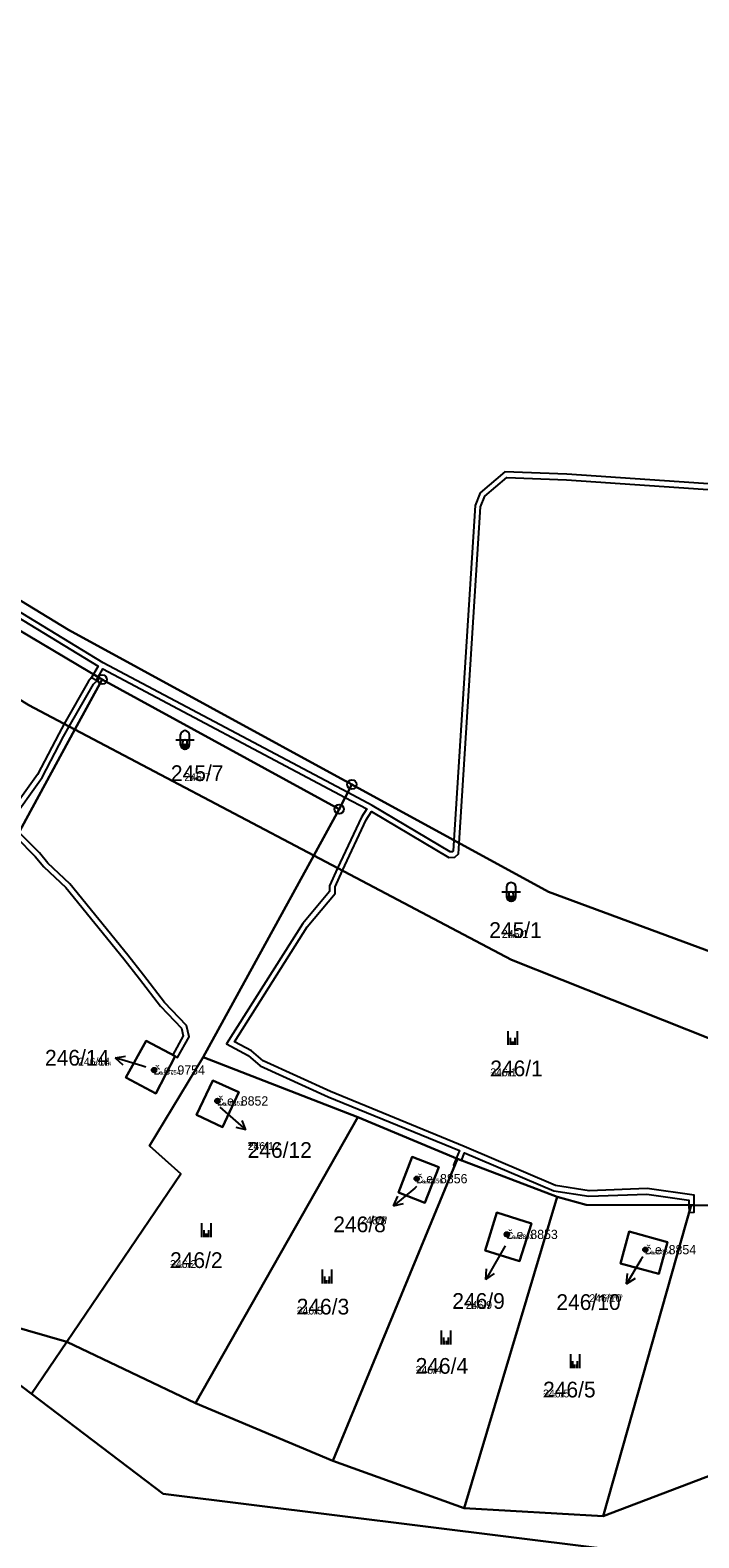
# Model space of a CAD drawing. Extents: x -759873 to -758487, y -975024 to -973516.
# Drawn here: x -759072.7 to -759000.3, y -974638.1 to -974475 of the extents above; entities that cross this region are included whole.
import ezdxf

# ---------------------------------------------------------------- set-up
doc = ezdxf.new("R2010")
doc.units = 0
for name, color, linetype in [('KAT_02_hranice parcel', 7, 'Continuous'), ('KAT_03_1000_st čísla parcelní', 7, 'Continuous'), ('KAT_03_1000_čísla parcelní', 7, 'Continuous'), ('KAT_03_1000_čísla popisná', 7, 'Continuous'), ('KAT_03_250_st čísla parcelní', 7, 'Continuous'), ('KAT_03_250_čísla parcelní', 7, 'Continuous'), ('KAT_03_250_čísla popisná', 7, 'Continuous'), ('KAT_03_500_st čísla parcelní', 7, 'Continuous'), ('KAT_03_500_čísla parcelní', 7, 'Continuous'), ('KAT_03_500_čísla popisná', 7, 'Continuous'), ('KAT_05_1000_značky kultur', 7, 'Continuous'), ('KAT_05_250_značky kultur', 7, 'Continuous'), ('KAT_05_500_značky kultur', 7, 'Continuous'), ('KAT_07_1000_značky budov', 7, 'Continuous'), ('KAT_07_250_značky budov', 7, 'Continuous'), ('KAT_07_500_značky budov', 7, 'Continuous'), ('KAT_10_věcná břemena', 7, 'Continuous'), ('KAT_11_značky bodu BP', 7, 'Continuous'), ('KAT_12_pomocná šipka', 7, 'Continuous'), ('KAT_14_plocha_budovy', 7, 'Continuous'), ('KAT_14_plocha_pozemek', 7, 'Continuous')]:
    doc.layers.add(name, color=color, linetype=linetype)

msp = doc.modelspace()

# ---------------------------------------------------------------- linework, layer by layer
at = {"layer": 'KAT_02_hranice parcel'}
for p, q in [((-759083.78, -974533.99), (-759064.86, -974545.21)), ((-759067.83, -974550.62), (-759064.86, -974545.21)), ((-759064.86, -974545.21), (-759039.21, -974559.23)), ((-759067.83, -974550.62), (-759041.97, -974564.24)), ((-759037.83, -974556.56), (-759039.21, -974559.23)), ((-759039.21, -974559.23), (-759041.97, -974564.24)), ((-759041.97, -974564.24), (-759053.94, -974586.07)), ((-759053.94, -974586.07), (-759037.2, -974592.53)), ((-759054.75, -974623.47), (-759037.2, -974592.53)), ((-759037.2, -974592.53), (-759026.41, -974597.05)), ((-759039.89, -974629.72), (-759026.41, -974597.05)), ((-759026.41, -974597.05), (-759015.6, -974601.17)), ((-759025.68, -974634.84), (-759015.6, -974601.17)), ((-759010.62, -974635.71), (-759001.08, -974602.07)), ((-759001.08, -974602.07), (-758984.89, -974602.12)), ((-759068.68, -974616.85), (-759072.53, -974622.47)), ((-759068.68, -974616.85), (-759054.75, -974623.47)), ((-759054.75, -974623.47), (-759039.89, -974629.72)), ((-759039.89, -974629.72), (-759025.68, -974634.84)), ((-759025.68, -974634.84), (-759010.62, -974635.71))]:
    msp.add_line(p, q, dxfattribs=at)
for points in [[(-759159.14, -974477.67), (-759138.76, -974497.06), (-759068.5, -974539.82), (-759037.83, -974556.56)], [(-759087, -974539.27), (-759072.82, -974547.99), (-759067.83, -974550.62)], [(-759100.16, -974608.12), (-759088.78, -974587.22), (-759079.24, -974570.06), (-759074.96, -974563.7), (-759067.83, -974550.62)], [(-759037.83, -974556.56), (-759016.55, -974568.17), (-758996.05, -974575.76)], [(-758998.76, -974584.19), (-759020.55, -974575.52), (-759041.97, -974564.24)], [(-759060.11, -974584.3), (-759062.32, -974588.27), (-759059.06, -974589.97), (-759056.96, -974585.95), (-759060.11, -974584.3)], [(-759072.53, -974622.47), (-759085.12, -974612.91), (-759119.49, -974608.48), (-759126.45, -974601.07), (-759123.88, -974586.97)], [(-759053.94, -974586.07), (-759059.73, -974595.66), (-759056.36, -974598.66), (-759068.68, -974616.85)], [(-759050.06, -974589.86), (-759051.86, -974593.64), (-759054.65, -974592.31), (-759052.9, -974588.58), (-759050.06, -974589.86)], [(-759028.4, -974597.95), (-759029.93, -974601.83), (-759032.79, -974600.7), (-759031.32, -974596.83), (-759028.4, -974597.95)], [(-759015.6, -974601.17), (-759012.48, -974602.03), (-759001.08, -974602.07)], [(-759019.7, -974608.14), (-759023.41, -974606.96), (-759022.14, -974602.86), (-759018.4, -974604.06), (-759019.7, -974608.14)], [(-759010.62, -974635.71), (-758989.44, -974627.68), (-758984.89, -974602.12)], [(-759003.65, -974606.07), (-759004.59, -974609.51), (-759008.75, -974608.38), (-759007.8, -974604.9), (-759003.65, -974606.07)], [(-759068.68, -974616.85), (-759079.63, -974613.7), (-759088.47, -974610.92), (-759100.16, -974608.12)], [(-759072.53, -974622.47), (-759058.27, -974633.29), (-759011.32, -974639.13), (-758985.91, -974649.95)]]:
    msp.add_lwpolyline(points, dxfattribs=at)
at = {"layer": 'KAT_03_1000_čísla popisná'}
for centre in [(-759059.25, -974587.45), (-759052.39, -974590.79), (-759030.82, -974599.2), (-759021.04, -974605.23), (-759006.06, -974606.88)]:
    msp.add_circle(centre, 0.25, dxfattribs=at)
at = {"layer": 'KAT_03_250_čísla popisná'}
for centre in [(-759059.25, -974587.45), (-759052.39, -974590.79), (-759030.82, -974599.2), (-759021.04, -974605.23), (-759006.06, -974606.88)]:
    msp.add_circle(centre, 0.0625, dxfattribs=at)
at = {"layer": 'KAT_03_500_čísla popisná'}
for centre in [(-759059.25, -974587.45), (-759052.39, -974590.79), (-759030.82, -974599.2), (-759021.04, -974605.23), (-759006.06, -974606.88)]:
    msp.add_circle(centre, 0.125, dxfattribs=at)
at = {"layer": 'KAT_05_1000_značky kultur'}
for p, q in [((-759056.41, -974551.24), (-759056.41, -974552.24)), ((-759055.41, -974552.24), (-759055.41, -974551.24)), ((-759056.91, -974551.74), (-759054.91, -974551.74)), ((-759021.09, -974567.68), (-759021.09, -974568.68)), ((-759020.09, -974568.68), (-759020.09, -974567.68)), ((-759021.59, -974568.18), (-759019.59, -974568.18)), ((-759020.91, -974584.73), (-759020.91, -974583.23)), ((-759019.91, -974584.73), (-759019.91, -974583.23)), ((-759054.08, -974605.51), (-759054.08, -974604.01)), ((-759053.08, -974605.51), (-759053.08, -974604.01)), ((-759041.01, -974610.54), (-759041.01, -974609.04)), ((-759040.01, -974610.54), (-759040.01, -974609.04)), ((-759028.13, -974617.12), (-759028.13, -974615.62)), ((-759027.13, -974617.12), (-759027.13, -974615.62)), ((-759014.14, -974619.68), (-759014.14, -974618.18)), ((-759013.14, -974619.68), (-759013.14, -974618.18))]:
    msp.add_line(p, q, dxfattribs=at)
for centre, start, end in [((-759055.91, -974551.24), 0, 180), ((-759055.91, -974552.24), 180, 359.9879), ((-759020.59, -974567.68), 0, 180), ((-759020.59, -974568.68), 180, 359.9879)]:
    msp.add_arc(centre, 0.5, start, end, dxfattribs=at)
at = {"layer": 'KAT_05_250_značky kultur'}
for p, q in [((-759056.16, -974552.49), (-759055.66, -974552.49)), ((-759056.04, -974552.37), (-759056.04, -974552.62)), ((-759055.78, -974552.62), (-759055.78, -974552.37)), ((-759020.84, -974568.93), (-759020.34, -974568.93)), ((-759020.72, -974568.81), (-759020.72, -974569.06)), ((-759020.46, -974569.06), (-759020.46, -974568.81)), ((-759020.53, -974584.73), (-759020.53, -974584.35)), ((-759020.28, -974584.73), (-759020.28, -974584.35)), ((-759053.7, -974605.51), (-759053.7, -974605.14)), ((-759053.45, -974605.51), (-759053.45, -974605.14)), ((-759040.63, -974610.54), (-759040.63, -974610.17)), ((-759040.38, -974610.54), (-759040.38, -974610.17)), ((-759027.75, -974617.12), (-759027.75, -974616.74)), ((-759027.5, -974617.12), (-759027.5, -974616.74)), ((-759013.76, -974619.68), (-759013.76, -974619.31)), ((-759013.51, -974619.68), (-759013.51, -974619.31))]:
    msp.add_line(p, q, dxfattribs=at)
for centre, start, end in [((-759055.91, -974552.37), 0, 180), ((-759055.91, -974552.62), 180, 359.9879), ((-759020.59, -974568.81), 0, 180), ((-759020.59, -974569.06), 180, 359.9879)]:
    msp.add_arc(centre, 0.125, start, end, dxfattribs=at)
at = {"layer": 'KAT_05_500_značky kultur'}
for p, q in [((-759056.41, -974552.24), (-759055.41, -974552.24)), ((-759056.16, -974551.99), (-759056.16, -974552.49)), ((-759055.66, -974552.49), (-759055.66, -974551.99)), ((-759021.09, -974568.68), (-759020.09, -974568.68)), ((-759020.84, -974568.43), (-759020.84, -974568.93)), ((-759020.34, -974568.93), (-759020.34, -974568.43)), ((-759020.66, -974584.73), (-759020.66, -974583.98)), ((-759020.16, -974584.73), (-759020.16, -974583.98)), ((-759053.83, -974605.51), (-759053.83, -974604.76)), ((-759053.33, -974605.51), (-759053.33, -974604.76)), ((-759040.76, -974610.54), (-759040.76, -974609.79)), ((-759040.26, -974610.54), (-759040.26, -974609.79)), ((-759027.88, -974617.12), (-759027.88, -974616.37)), ((-759027.38, -974617.12), (-759027.38, -974616.37)), ((-759013.89, -974619.68), (-759013.89, -974618.93)), ((-759013.39, -974619.68), (-759013.39, -974618.93))]:
    msp.add_line(p, q, dxfattribs=at)
for centre, start, end in [((-759055.91, -974551.99), 0, 180), ((-759055.91, -974552.49), 180, 359.9879), ((-759020.59, -974568.43), 0, 180), ((-759020.59, -974568.93), 180, 359.9879)]:
    msp.add_arc(centre, 0.25, start, end, dxfattribs=at)
at = {"layer": 'KAT_07_1000_značky budov'}
for centre in [(-759059.26, -974587.45), (-759052.4, -974590.79), (-759030.83, -974599.2), (-759021.05, -974605.23), (-759006.07, -974606.88)]:
    msp.add_circle(centre, 0.175, dxfattribs=at)
at = {"layer": 'KAT_07_250_značky budov'}
for centre in [(-759059.25, -974587.45), (-759052.39, -974590.79), (-759030.82, -974599.2), (-759021.04, -974605.23), (-759006.06, -974606.88)]:
    msp.add_circle(centre, 0.0437, dxfattribs=at)
at = {"layer": 'KAT_07_500_značky budov'}
for centre in [(-759059.25, -974587.45), (-759052.39, -974590.79), (-759030.82, -974599.2), (-759021.04, -974605.23), (-759006.06, -974606.88)]:
    msp.add_circle(centre, 0.0875, dxfattribs=at)
at = {"layer": 'KAT_10_věcná břemena'}
for points in [[(-759099.57, -974522.91), (-759065.31, -974543.77), (-759065.82, -974544.64), (-759066.02, -974544.99), (-759065.5, -974545.29), (-759065.3, -974544.95), (-759064.79, -974544.07), (-759038.55, -974557.96), (-759036.23, -974559.19), (-759036.8, -974560.08), (-759039.38, -974565.6), (-759040.26, -974567.51), (-759040.24, -974568.15), (-759043.14, -974571.6), (-759051.41, -974584.63), (-759049.05, -974585.89), (-759047.77, -974586.98), (-759040.4, -974590.34), (-759026.18, -974596.16), (-759026.53, -974597), (-759026.41, -974597.05), (-759025.97, -974597.22), (-759025.63, -974596.4), (-759015.95, -974600.53), (-759012.19, -974601.1), (-759005.89, -974600.86), (-759001.36, -974601.51), (-759001.34, -974602.07), (-759000.76, -974602.07), (-759000.76, -974600.99), (-759005.85, -974600.26), (-759012.15, -974600.5), (-759015.79, -974599.95), (-759025.67, -974595.72), (-759040.16, -974589.78), (-759047.45, -974586.46), (-759048.71, -974585.39), (-759050.55, -974584.41), (-759042.66, -974571.96), (-759039.64, -974568.37), (-759039.66, -974567.63), (-759038.84, -974565.88), (-759036.28, -974560.38), (-759035.7, -974559.49), (-759027.34, -974564.45), (-759026.7, -974564.43), (-759026.27, -974564.06), (-759026.2, -974562.91), (-759026.78, -974562.59), (-759026.85, -974563.76), (-759026.94, -974563.83), (-759027.18, -974563.85), (-759035.65, -974558.82), (-759038.28, -974557.43), (-759064.75, -974543.41), (-759099.77, -974522.09)], [(-758968.02, -974526.18), (-759014.55, -974523.01), (-759021.27, -974522.74), (-759023.95, -974525.01), (-759024.49, -974526.4), (-759026.78, -974562.59), (-759026.2, -974562.91), (-759023.89, -974526.52), (-759023.45, -974525.37), (-759021.07, -974523.34), (-759014.59, -974523.61), (-758968.08, -974526.78)], [(-759074.87, -974560.71), (-759071.36, -974555.82), (-759069.07, -974551.39), (-759068.45, -974550.3), (-759065.82, -974545.7), (-759065.24, -974545.18), (-759065.17, -974545.03), (-759065.82, -974544.64), (-759066.02, -974544.99), (-759066.34, -974545.4), (-759068.97, -974550.02), (-759069.57, -974551.07), (-759071.86, -974555.5), (-759075.29, -974560.28)], [(-759074.18, -974562.27), (-759072.11, -974564.37), (-759071.18, -974565.47), (-759068.82, -974567.72), (-759062.54, -974575.43), (-759060.84, -974577.57), (-759058.57, -974580.55), (-759056.28, -974582.92), (-759056.1, -974583.76), (-759057.22, -974585.81), (-759056.96, -974585.95), (-759056.7, -974586.09), (-759055.46, -974583.84), (-759055.74, -974582.62), (-759058.11, -974580.15), (-759060.38, -974577.19), (-759062.08, -974575.03), (-759068.38, -974567.32), (-759070.74, -974565.07), (-759071.67, -974563.97), (-759073.88, -974561.72)]]:
    msp.add_lwpolyline(points, dxfattribs=at)
for points in [[(-759026.71, -974597.78), (-759026.41, -974597.05), (-759026.53, -974597), (-759026.83, -974597.73)], [(-759001.34, -974602.07), (-759001.3, -974602.86), (-759001.08, -974602.07)], [(-759001.3, -974602.86), (-759000.76, -974602.84), (-759000.76, -974602.07), (-759001.08, -974602.07)]]:
    msp.add_lwpolyline(points, close=True, dxfattribs=at)
at = {"layer": 'KAT_11_značky bodu BP'}
for centre, radius in [((-759064.86, -974545.21), 0.5), ((-759064.86, -974545.21), 0.0303), ((-759037.83, -974556.56), 0.5), ((-759037.83, -974556.56), 0.0303), ((-759039.21, -974559.23), 0.5), ((-759039.21, -974559.23), 0.0303)]:
    msp.add_circle(centre, radius, dxfattribs=at)
at = {"layer": 'KAT_12_pomocná šipka'}
for p, q in [((-759063.45, -974586.12), (-759062.35, -974585.94)), ((-759060.58, -974587), (-759063.45, -974586.12)), ((-759063.45, -974586.12), (-759062.64, -974586.89)), ((-759060.16, -974587.13), (-759060.58, -974587)), ((-759052.13, -974591.46), (-759051.56, -974591.96)), ((-759051.56, -974591.96), (-759049.3, -974593.93)), ((-759049.3, -974593.93), (-759050.38, -974593.65)), ((-759049.3, -974593.93), (-759049.72, -974592.89)), ((-759031.02, -974600.21), (-759033.32, -974602.14)), ((-759030.84, -974600.06), (-759031.02, -974600.21)), ((-759033.32, -974602.14), (-759032.87, -974601.11)), ((-759033.32, -974602.14), (-759032.23, -974601.88)), ((-759021.24, -974606.48), (-759021.82, -974607.49)), ((-759021.82, -974607.49), (-759023.32, -974610.09)), ((-759006.54, -974607.99), (-759008.09, -974610.56)), ((-759006.34, -974607.65), (-759006.54, -974607.99)), ((-759023.32, -974610.09), (-759023.25, -974608.97)), ((-759023.32, -974610.09), (-759022.39, -974609.47)), ((-759008.09, -974610.56), (-759008, -974609.45)), ((-759008.09, -974610.56), (-759007.14, -974609.96))]:
    msp.add_line(p, q, dxfattribs=at)
at = {"layer": 'KAT_14_plocha_budovy'}
for points in [[(-759062.32, -974588.27), (-759059.06, -974589.97), (-759056.96, -974585.95), (-759060.11, -974584.3)], [(-759054.65, -974592.31), (-759051.86, -974593.64), (-759050.06, -974589.86), (-759052.9, -974588.58)], [(-759032.79, -974600.7), (-759029.93, -974601.83), (-759028.4, -974597.95), (-759031.32, -974596.83)], [(-759023.41, -974606.96), (-759019.7, -974608.14), (-759018.4, -974604.06), (-759022.14, -974602.86)], [(-759008.75, -974608.38), (-759004.59, -974609.51), (-759003.65, -974606.07), (-759007.8, -974604.9)]]:
    msp.add_lwpolyline(points, close=True, dxfattribs=at)
at = {"layer": 'KAT_14_plocha_pozemek'}
for points in [[(-759164.42, -974455.5), (-759159.14, -974477.67), (-759138.76, -974497.06), (-759068.5, -974539.82), (-759037.83, -974556.56), (-759016.55, -974568.17), (-758996.05, -974575.76)], [(-758985.91, -974649.95), (-759011.32, -974639.13), (-759058.27, -974633.29), (-759072.53, -974622.47), (-759085.12, -974612.91), (-759119.49, -974608.48), (-759126.45, -974601.07), (-759123.88, -974586.97), (-759138.78, -974574.64), (-759149.95, -974565.4), (-759151.3, -974564.28), (-759155.66, -974538.03), (-759168.27, -974530.82)]]:
    msp.add_lwpolyline(points, dxfattribs=at)
for points in [[(-759100.28, -974524), (-759083.78, -974533.99), (-759064.86, -974545.21), (-759039.21, -974559.23), (-759037.83, -974556.56), (-759068.5, -974539.82), (-759138.76, -974497.06), (-759159.14, -974477.67), (-759150.51, -974493.42), (-759122.84, -974510.23)], [(-759087, -974539.27), (-759072.82, -974547.99), (-759067.83, -974550.62), (-759064.86, -974545.21), (-759083.78, -974533.99)], [(-759067.83, -974550.62), (-759072.82, -974547.99), (-759087, -974539.27), (-759093.17, -974549.44), (-759100.94, -974559.67), (-759106.9, -974566.95), (-759110.32, -974570.69), (-759122.47, -974587.73), (-759119.12, -974590.77), (-759122.45, -974602.82), (-759100.16, -974608.12), (-759088.78, -974587.22), (-759079.24, -974570.06), (-759074.96, -974563.7)], [(-759067.83, -974550.62), (-759041.97, -974564.24), (-759039.21, -974559.23), (-759064.86, -974545.21)], [(-759053.94, -974586.07), (-759041.97, -974564.24), (-759067.83, -974550.62), (-759074.96, -974563.7), (-759079.24, -974570.06), (-759088.78, -974587.22), (-759100.16, -974608.12), (-759088.47, -974610.92), (-759079.63, -974613.7), (-759068.68, -974616.85), (-759056.36, -974598.66), (-759059.73, -974595.66)], [(-759039.21, -974559.23), (-759041.97, -974564.24), (-759020.55, -974575.52), (-758998.76, -974584.19), (-758996.05, -974575.76), (-759016.55, -974568.17), (-759037.83, -974556.56)], [(-758968.42, -974607.24), (-758984.03, -974596.47), (-758998.76, -974584.19), (-759020.55, -974575.52), (-759041.97, -974564.24), (-759053.94, -974586.07), (-759037.2, -974592.53), (-759026.41, -974597.05), (-759015.6, -974601.17), (-759012.48, -974602.03), (-759001.08, -974602.07), (-758984.89, -974602.12)], [(-759060.11, -974584.3), (-759062.32, -974588.27), (-759059.06, -974589.97), (-759056.96, -974585.95)], [(-759060.11, -974584.3), (-759056.96, -974585.95), (-759059.06, -974589.97), (-759062.32, -974588.27)], [(-759088.47, -974610.92), (-759100.16, -974608.12), (-759122.45, -974602.82), (-759119.12, -974590.77), (-759122.47, -974587.73), (-759123.88, -974586.97), (-759126.45, -974601.07), (-759119.49, -974608.48), (-759085.12, -974612.91), (-759072.53, -974622.47), (-759068.68, -974616.85), (-759079.63, -974613.7)], [(-759053.94, -974586.07), (-759059.73, -974595.66), (-759056.36, -974598.66), (-759068.68, -974616.85), (-759054.75, -974623.47), (-759037.2, -974592.53)], [(-759050.06, -974589.86), (-759051.86, -974593.64), (-759054.65, -974592.31), (-759052.9, -974588.58)], [(-759050.06, -974589.86), (-759052.9, -974588.58), (-759054.65, -974592.31), (-759051.86, -974593.64)], [(-759039.89, -974629.72), (-759026.41, -974597.05), (-759037.2, -974592.53), (-759054.75, -974623.47)], [(-759025.68, -974634.84), (-759015.6, -974601.17), (-759026.41, -974597.05), (-759039.89, -974629.72)], [(-759028.4, -974597.95), (-759029.93, -974601.83), (-759032.79, -974600.7), (-759031.32, -974596.83)], [(-759028.4, -974597.95), (-759031.32, -974596.83), (-759032.79, -974600.7), (-759029.93, -974601.83)], [(-759001.08, -974602.07), (-759012.48, -974602.03), (-759015.6, -974601.17), (-759025.68, -974634.84), (-759010.62, -974635.71)], [(-759068.68, -974616.85), (-759072.53, -974622.47), (-759058.27, -974633.29), (-759011.32, -974639.13), (-758985.91, -974649.95), (-758968.42, -974607.24), (-758984.89, -974602.12), (-758989.44, -974627.68), (-759010.62, -974635.71), (-759025.68, -974634.84), (-759039.89, -974629.72), (-759054.75, -974623.47)], [(-759019.7, -974608.14), (-759023.41, -974606.96), (-759022.14, -974602.86), (-759018.4, -974604.06)], [(-759019.7, -974608.14), (-759018.4, -974604.06), (-759022.14, -974602.86), (-759023.41, -974606.96)], [(-758984.89, -974602.12), (-759001.08, -974602.07), (-759010.62, -974635.71), (-758989.44, -974627.68)], [(-759003.65, -974606.07), (-759004.59, -974609.51), (-759008.75, -974608.38), (-759007.8, -974604.9)], [(-759003.65, -974606.07), (-759007.8, -974604.9), (-759008.75, -974608.38), (-759004.59, -974609.51)]]:
    msp.add_lwpolyline(points, close=True, dxfattribs=at)

# ---------------------------------------------------------------- texts
at = {"layer": 'KAT_03_1000_st čísla parcelní'}
for s, p in [('246/14', (-759071.06, -974586.97)), ('246/12', (-759049.12, -974596.95)), ('246/8', (-759039.85, -974604.99)), ('246/9', (-759026.96, -974613.28)), ('246/10', (-759015.69, -974613.4))]:
    msp.add_text(s, height=1.7, dxfattribs=at).set_placement(p)
at = {"layer": 'KAT_03_1000_čísla parcelní'}
for s, p in [('245/7', (-759057.43, -974556.19)), ('245/1', (-759022.96, -974573.16)), ('246/1', (-759022.85, -974588.12)), ('246/2', (-759057.52, -974608.86)), ('246/3', (-759043.81, -974613.89)), ('246/4', (-759030.93, -974620.3)), ('246/5', (-759017.13, -974622.86))]:
    msp.add_text(s, height=1.7, dxfattribs=at).set_placement(p)
at = {"layer": 'KAT_03_1000_čísla popisná'}
for s, p in [('č.e. 9754', (-759059.25, -974587.95)), ('č.e. 8852', (-759052.39, -974591.29)), ('č.e. 8856', (-759030.82, -974599.7)), ('č.e. 8853', (-759021.04, -974605.73)), ('č.e. 8854', (-759006.06, -974607.38))]:
    msp.add_text(s, height=1, dxfattribs=at).set_placement(p)
at = {"layer": 'KAT_03_250_st čísla parcelní'}
for s, p in [('246/14', (-759065.7, -974586.97)), ('246/12', (-759049.12, -974595.68)), ('246/8', (-759035.47, -974603.72)), ('246/10', (-759010.33, -974612.13)), ('246/9', (-759024.77, -974613.28))]:
    msp.add_text(s, height=0.425, dxfattribs=at).set_placement(p)
at = {"layer": 'KAT_03_250_čísla parcelní'}
for s, p in [('245/7', (-759055.25, -974556.19)), ('245/1', (-759020.9, -974573.16)), ('246/1', (-759022.85, -974588.12)), ('246/2', (-759057.52, -974608.86)), ('246/3', (-759043.81, -974613.89)), ('246/4', (-759030.93, -974620.3)), ('246/5', (-759017.13, -974622.86))]:
    msp.add_text(s, height=0.425, dxfattribs=at).set_placement(p)
at = {"layer": 'KAT_03_250_čísla popisná'}
for s, p in [('č.e. 9754', (-759059.25, -974587.95)), ('č.e. 8852', (-759052.39, -974591.29)), ('č.e. 8856', (-759030.82, -974599.7)), ('č.e. 8853', (-759021.04, -974605.73)), ('č.e. 8854', (-759006.06, -974607.38))]:
    msp.add_text(s, height=0.25, dxfattribs=at).set_placement(p)
at = {"layer": 'KAT_03_500_st čísla parcelní'}
for s, p in [('246/14', (-759067.49, -974586.97)), ('246/12', (-759049.12, -974596.1)), ('246/8', (-759036.93, -974604.14)), ('246/10', (-759012.12, -974612.55)), ('246/9', (-759025.5, -974613.28))]:
    msp.add_text(s, height=0.85, dxfattribs=at).set_placement(p)
at = {"layer": 'KAT_03_500_čísla parcelní'}
for s, p in [('245/7', (-759055.97, -974556.19)), ('245/1', (-759021.59, -974573.16)), ('246/1', (-759022.85, -974588.12)), ('246/2', (-759057.52, -974608.86)), ('246/3', (-759043.81, -974613.89)), ('246/4', (-759030.93, -974620.3)), ('246/5', (-759017.13, -974622.86))]:
    msp.add_text(s, height=0.85, dxfattribs=at).set_placement(p)
at = {"layer": 'KAT_03_500_čísla popisná'}
for s, p in [('č.e. 9754', (-759059.25, -974587.95)), ('č.e. 8852', (-759052.39, -974591.29)), ('č.e. 8856', (-759030.82, -974599.7)), ('č.e. 8853', (-759021.04, -974605.73)), ('č.e. 8854', (-759006.06, -974607.38))]:
    msp.add_text(s, height=0.5, dxfattribs=at).set_placement(p)

doc.saveas('drawing.dxf')
